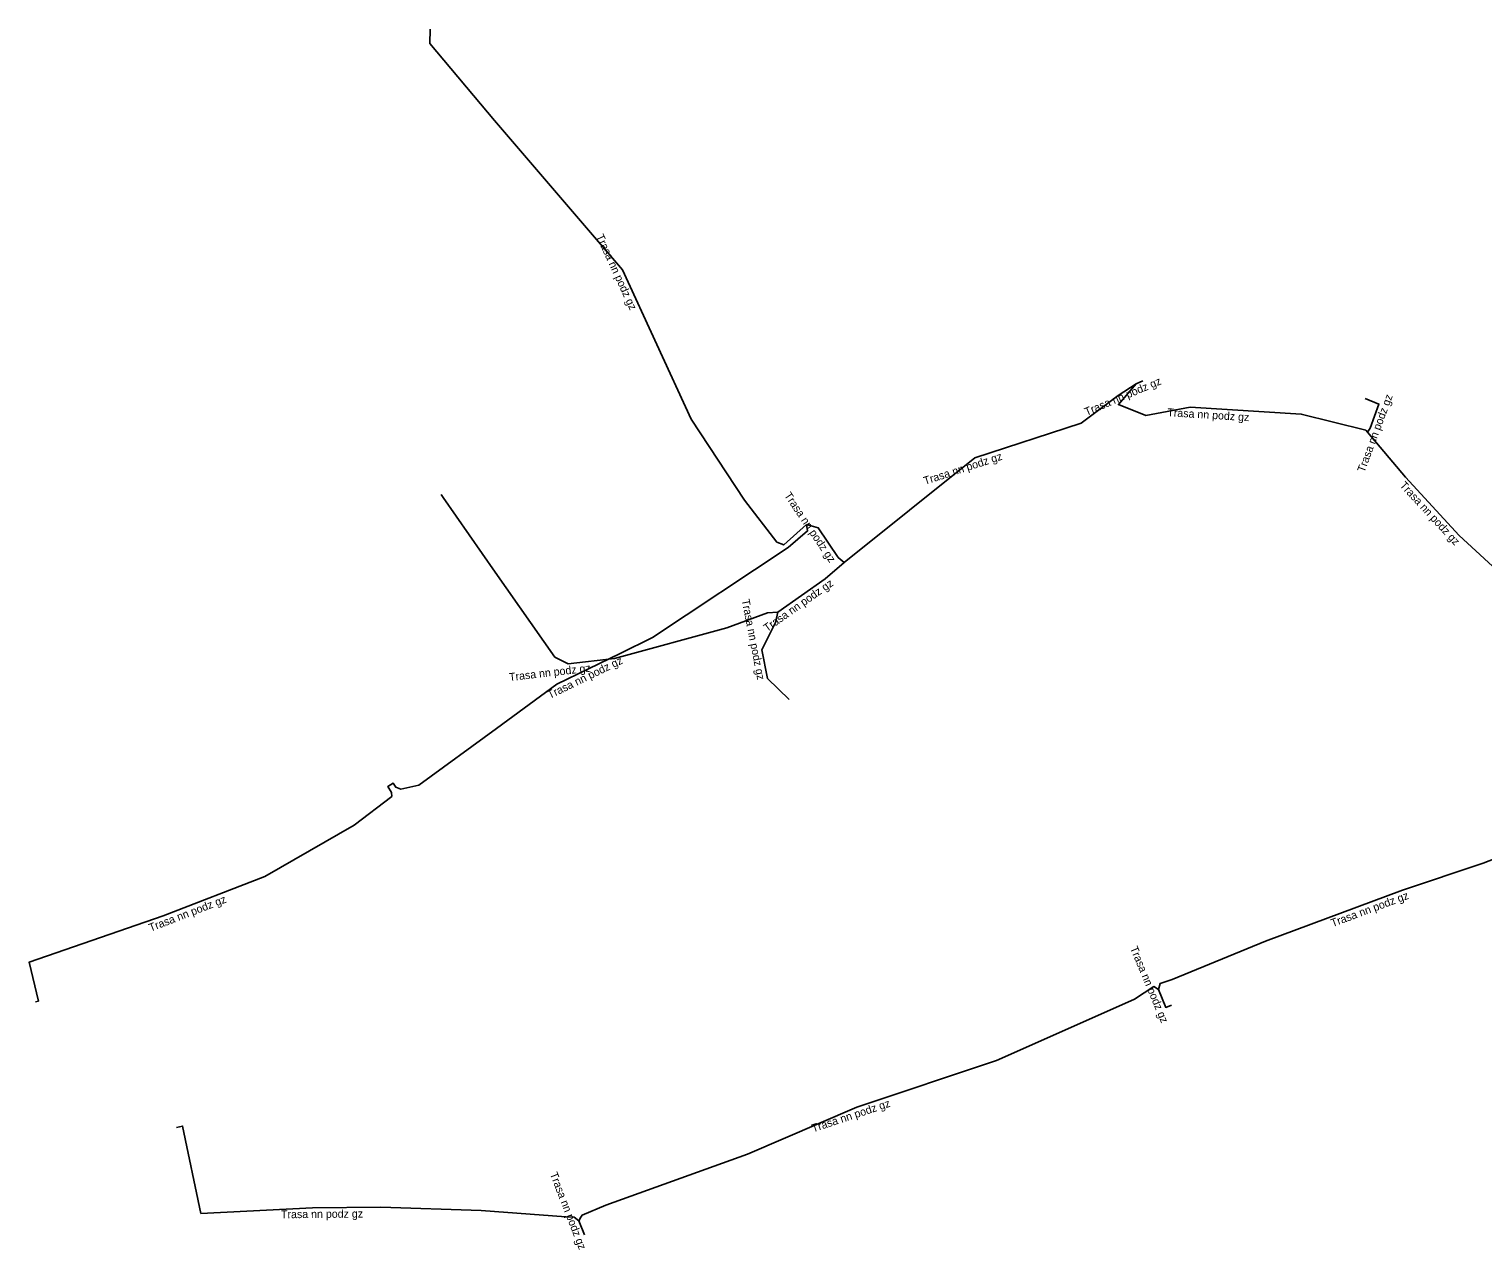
# Model space of a CAD drawing. Extents: x -484846 to -484244, y -1128177 to -1127608.
# Drawn here: x -484845.6 to -484754.1, y -1127685 to -1127608.1 of the extents above; entities that cross this region are included whole.
import ezdxf

# ---------------------------------------------------------------- set-up
doc = ezdxf.new("R2010")
doc.units = 0
doc.layers.add('Popiskový text - Ostatní atributy Trasy', color=7, linetype='Continuous')
doc.layers.add('Spojnice NN', color=7, linetype='Continuous')

msp = doc.modelspace()

# ---------------------------------------------------------------- linework, layer by layer
at = {"layer": 'Spojnice NN'}
for points in [[(-484820.39, -1127608.14), (-484820.422, -1127609.059), (-484816.34, -1127613.9), (-484808.28, -1127623.3), (-484803.97, -1127632.71), (-484800.61, -1127637.81), (-484798.57, -1127640.46), (-484798.14, -1127640.63), (-484796.7, -1127639.35)], [(-484794.33, -1127641.73), (-484786.1, -1127635.14), (-484779.41, -1127632.96), (-484777.09, -1127631.21), (-484775.96, -1127630.48)], [(-484775.96, -1127630.48), (-484777.07, -1127631.79), (-484775.34, -1127632.47), (-484772.55, -1127631.96), (-484765.56, -1127632.39), (-484761.5, -1127633.4), (-484761.387, -1127633.535)], [(-484775.96, -1127630.48), (-484775.535, -1127630.3)], [(-484761.387, -1127633.535), (-484761.237, -1127633.271), (-484760.678, -1127631.756), (-484761.54, -1127631.41)], [(-484761.387, -1127633.535), (-484759.01, -1127636.37), (-484755.62, -1127640.04), (-484752.72, -1127642.7), (-484750.74, -1127644.7)], [(-484798.52, -1127644.86), (-484799.16, -1127644.91), (-484801.72, -1127645.86), (-484808.8, -1127647.78), (-484811.7, -1127648.12), (-484812.54, -1127647.7), (-484816.3, -1127642.35), (-484819.584, -1127637.636), (-484819.705, -1127637.462)], [(-484796.7, -1127639.35), (-484796.64, -1127639.75), (-484797.85, -1127640.8), (-484806.4, -1127646.45), (-484808.44, -1127647.46), (-484812.41, -1127649.39), (-484816.22, -1127652.2), (-484821.1, -1127655.76), (-484822.24, -1127656.01), (-484822.558, -1127655.894), (-484822.728, -1127655.631), (-484822.896, -1127655.74)], [(-484796.7, -1127639.35), (-484795.966, -1127639.559), (-484794.71, -1127641.419), (-484794.33, -1127641.73)], [(-484794.33, -1127641.73), (-484795.54, -1127642.76), (-484798.52, -1127644.86)], [(-484798.52, -1127644.86), (-484798.66, -1127645.52), (-484799.51, -1127647.24), (-484799.157, -1127649.037), (-484797.806, -1127650.355)], [(-484822.896, -1127655.74), (-484823.064, -1127655.849), (-484822.826, -1127656.216), (-484822.8, -1127656.47), (-484825.18, -1127658.27), (-484830.8, -1127661.52), (-484837.19, -1127663.99), (-484845.638, -1127666.915), (-484845.047, -1127669.355), (-484845.241, -1127669.401)], [(-484746.597, -1127659.523), (-484747.004, -1127657.903), (-484754.11, -1127660.67), (-484759.19, -1127662.37), (-484767.82, -1127665.58), (-484773.69, -1127668), (-484774.44, -1127668.25), (-484774.56, -1127668.63)], [(-484774.56, -1127668.63), (-484774.851, -1127668.441), (-484776.06, -1127669.23), (-484780.07, -1127671.03), (-484784.75, -1127673.1), (-484793.54, -1127676.03), (-484800.42, -1127679), (-484809.34, -1127682.21), (-484810.83, -1127682.84), (-484810.903, -1127682.972), (-484811.03, -1127683.2)], [(-484774.56, -1127668.63), (-484774.092, -1127669.753), (-484773.738, -1127669.607)], [(-484811.03, -1127683.2), (-484811.332, -1127682.972), (-484811.86, -1127682.94), (-484817.18, -1127682.55), (-484823.49, -1127682.33), (-484827.79, -1127682.37), (-484834.82, -1127682.73), (-484835.977, -1127677.229), (-484836.368, -1127677.311)], [(-484811.03, -1127683.2), (-484810.689, -1127684.084)]]:
    msp.add_lwpolyline(points, dxfattribs=at)

# ---------------------------------------------------------------- texts
at = {"layer": 'Popiskový text - Ostatní atributy Trasy'}
for rotation, p in [(294.60889, (-484809.96, -1127621.193)), (22.95409, (-484779.08, -1127632.507)), (69.74403, (-484761.588, -1127636.098)), (356.4798, (-484774.006, -1127632.521)), (18.04869, (-484789.247, -1127636.849)), (304.01221, (-484798.131, -1127637.512)), (312.72884, (-484759.4, -1127636.906)), (35.17228, (-484799.189, -1127646.126)), (281.11359, (-484800.79, -1127644.097)), (6.68691, (-484815.396, -1127649.208)), (25.92652, (-484812.862, -1127650.332)), (21.13358, (-484837.99, -1127664.996)), (20.4031, (-484763.594, -1127664.702)), (292.62168, (-484776.35, -1127666.024)), (18.43495, (-484796.286, -1127677.63)), (291.09395, (-484812.868, -1127680.243)), (0.53297, (-484829.78, -1127683.038))]:
    msp.add_text('Trasa nn podz gz', height=0.5, rotation=rotation, dxfattribs=at).set_placement(p)

doc.saveas('drawing.dxf')
